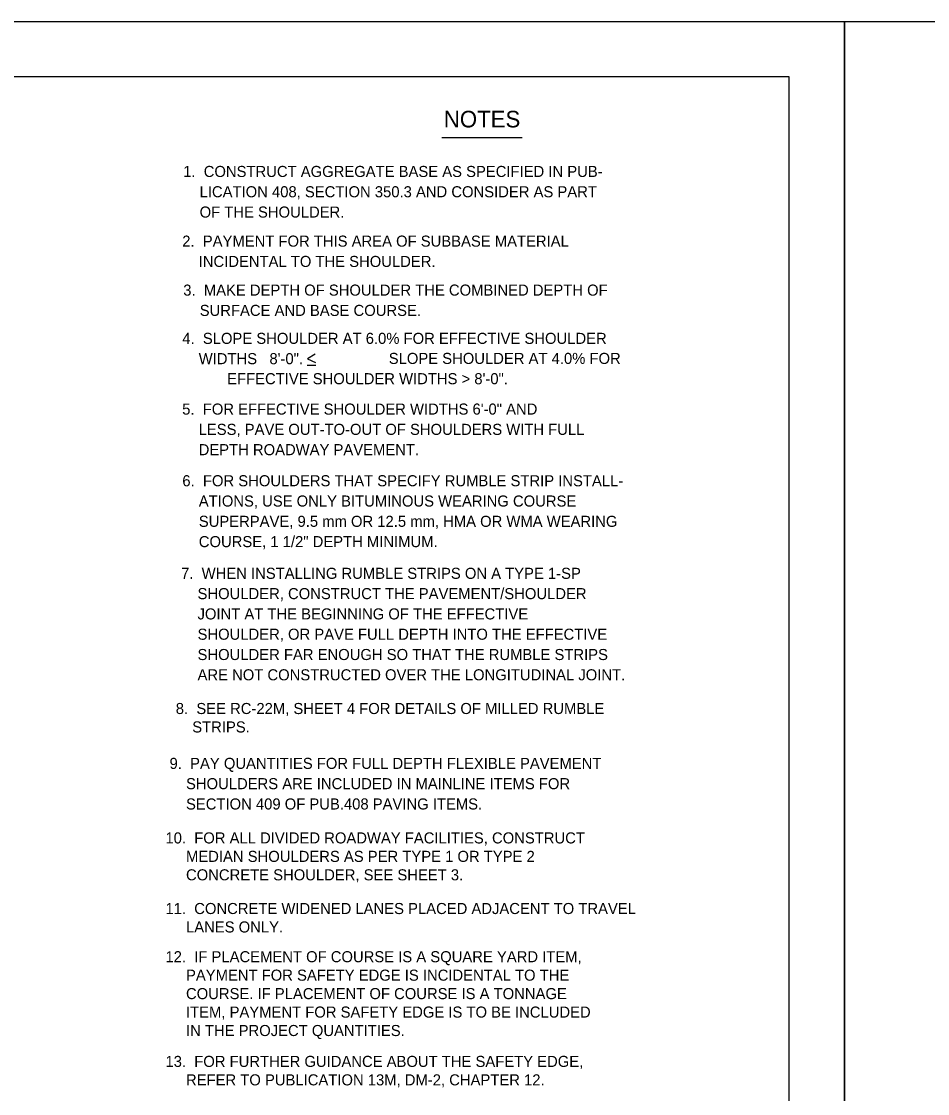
# Model space of a CAD drawing. Extents: x 638216 to 639962, y 297510 to 299292.
# Drawn here: x 638833.9 to 639079.4, y 299001.7 to 299292.2 of the extents above; entities that cross this region are included whole.
import ezdxf

# ---------------------------------------------------------------- set-up
doc = ezdxf.new("R2010")
doc.units = 0
for name, color, linetype in [('1', 7, 'Continuous'), ('2', 7, 'Continuous'), ('3', 7, 'Continuous'), ('PLT-BNDY', 7, 'Continuous')]:
    doc.layers.add(name, color=color, linetype=linetype)

msp = doc.modelspace()

# ---------------------------------------------------------------- linework, layer by layer
at = {"layer": '1'}
msp.add_line((638911.28, 299199.1), (638913.63, 299199.1), dxfattribs=at)
msp.add_lwpolyline([(639041.88, 298713.24), (639041.88, 299277.24), (638255.88, 299277.24), (638255.88, 298713.24), (639041.88, 298713.24), (639041.88, 298739.6), (638841.88, 298739.6), (638841.88, 298804.28), (639041.88, 298804.28), (639041.88, 298833.24), (638841.88, 298833.24), (638841.88, 298713.24), (638920.69, 298713.24), (638920.69, 298739.6), (638920.69, 298713.24), (638997.69, 298713.24), (638997.69, 298739.6), (638997.69, 298727.28), (639041.88, 298727.28)], dxfattribs=at)
at = {"layer": '2'}
msp.add_line((638947.79, 299260.78), (638969.52, 299260.78), dxfattribs=at)
at = {"layer": '3'}
for p, q in [((638913.46, 299202.07), (638911.35, 299200.79)), ((638911.35, 299200.79), (638913.58, 299199.84))]:
    msp.add_line(p, q, dxfattribs=at)
at = {"layer": 'PLT-BNDY'}
for points in [[(638215.88, 299292.24), (639056.88, 299292.24), (639056.88, 298698.24), (638215.88, 298698.24)], [(639056.88, 299292.24), (639897.88, 299292.24), (639897.88, 298698.24), (639056.88, 298698.24)]]:
    msp.add_lwpolyline(points, close=True, dxfattribs=at)

# ---------------------------------------------------------------- texts
at = {"layer": '1'}
for s, p in [('6.  FOR SHOULDERS THAT SPECIFY RUMBLE STRIP INSTALL-', (638877.46, 299166.28)), ('    ATIONS, USE ONLY BITUMINOUS WEARING COURSE ', (638877.46, 299160.78)), ('    SUPERPAVE, 9.5 mm OR 12.5 mm, HMA OR WMA WEARING ', (638877.46, 299155.28)), ('    COURSE, 1 1/2" DEPTH MINIMUM.', (638877.46, 299149.78)), ('7.  WHEN INSTALLING RUMBLE STRIPS ON A TYPE 1-SP', (638877.12, 299141.19)), ('    SHOULDER, CONSTRUCT THE PAVEMENT/SHOULDER', (638877.12, 299135.69)), ('    JOINT AT THE BEGINNING OF THE EFFECTIVE', (638877.12, 299130.19)), ('    SHOULDER, OR PAVE FULL DEPTH INTO THE EFFECTIVE', (638877.12, 299124.69)), ('    SHOULDER FAR ENOUGH SO THAT THE RUMBLE STRIPS', (638877.12, 299119.19)), ('    ARE NOT CONSTRUCTED OVER THE LONGITUDINAL JOINT. ', (638877.12, 299113.69))]:
    msp.add_text(s, height=3, dxfattribs=at).set_placement(p)
at = {"layer": '3'}
for s, height, p in [('NOTES', 4.5, (638948.32, 299263.52)), ('1.  CONSTRUCT AGGREGATE BASE AS SPECIFIED IN PUB-', 3, (638877.68, 299250.09)), ('    LICATION 408, SECTION 350.3 AND CONSIDER AS PART', 3, (638877.68, 299244.59)), ('    OF THE SHOULDER.', 3, (638877.68, 299239.09)), ('2.  PAYMENT FOR THIS AREA OF SUBBASE MATERIAL', 3, (638877.43, 299231.21)), ('    INCIDENTAL TO THE SHOULDER.', 3, (638877.43, 299225.71)), ('3.  MAKE DEPTH OF SHOULDER THE COMBINED DEPTH OF', 3, (638877.71, 299217.94)), ('    SURFACE AND BASE COURSE.', 3, (638877.71, 299212.44)), ('4.  SLOPE SHOULDER AT 6.0% FOR EFFECTIVE SHOULDER', 3, (638877.44, 299204.86)), ('    WIDTHS   8\'-0".', 3, (638877.44, 299199.36)), ('  SLOPE SHOULDER AT 4.0% FOR', 3, (638931.17, 299199.43)), ('EFFECTIVE SHOULDER WIDTHS > 8\'-0".', 3, (638889.61, 299193.93)), ('5.  FOR EFFECTIVE SHOULDER WIDTHS 6\'-0" AND', 3, (638877.42, 299185.7)), ('    LESS, PAVE OUT-TO-OUT OF SHOULDERS WITH FULL', 3, (638877.42, 299180.2)), ('    DEPTH ROADWAY PAVEMENT.', 3, (638877.42, 299174.7)), ('8.  SEE RC-22M, SHEET 4 FOR DETAILS OF MILLED RUMBLE', 3, (638875.68, 299104.56)), ('    STRIPS.', 3, (638875.68, 299099.56)), (' 9.  PAY QUANTITIES FOR FULL DEPTH FLEXIBLE PAVEMENT', 3, (638872.88, 299089.69)), ('     SHOULDERS ARE INCLUDED IN MAINLINE ITEMS FOR ', 3, (638872.88, 299084.19)), ('     SECTION 409 OF PUB.408 PAVING ITEMS.', 3, (638872.88, 299078.69)), ('10.  FOR ALL DIVIDED ROADWAY FACILITIES, CONSTRUCT', 3, (638872.88, 299069.49)), ('     MEDIAN SHOULDERS AS PER TYPE 1 OR TYPE 2 ', 3, (638872.88, 299064.49)), ('     CONCRETE SHOULDER, SEE SHEET 3.', 3, (638872.88, 299059.49)), ('11.  CONCRETE WIDENED LANES PLACED ADJACENT TO TRAVEL', 3, (638872.88, 299050.36)), ('     LANES ONLY.', 3, (638872.88, 299045.36)), ('12.  IF PLACEMENT OF COURSE IS A SQUARE YARD ITEM, ', 3, (638872.88, 299037.3)), ('     PAYMENT FOR SAFETY EDGE IS INCIDENTAL TO THE', 3, (638872.88, 299032.3)), ('     COURSE. IF PLACEMENT OF COURSE IS A TONNAGE', 3, (638872.88, 299027.3)), ('     ITEM, PAYMENT FOR SAFETY EDGE IS TO BE INCLUDED', 3, (638872.88, 299022.3)), ('     IN THE PROJECT QUANTITIES.', 3, (638872.88, 299017.3)), ('13.  FOR FURTHER GUIDANCE ABOUT THE SAFETY EDGE,', 3, (638872.88, 299008.93)), ('     REFER TO PUBLICATION 13M, DM-2, CHAPTER 12.', 3, (638872.88, 299003.93))]:
    msp.add_text(s, height=height, dxfattribs=at).set_placement(p)

doc.saveas('drawing.dxf')
